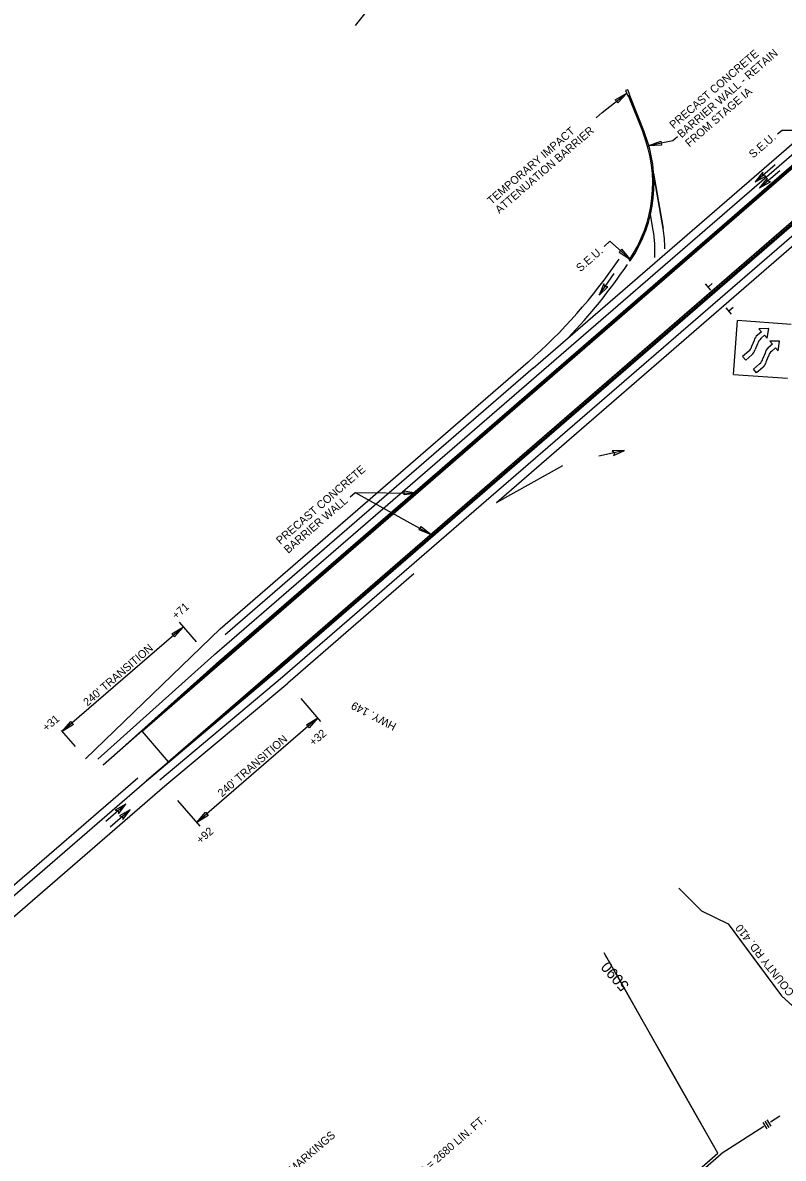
# Model space of a CAD drawing. Extents: x 259983 to 267998, y 211467 to 219827.
# Drawn here: x 261307 to 262447, y 216417 to 218119 of the extents above; entities that cross this region are included whole.
import ezdxf

# ---------------------------------------------------------------- set-up
doc = ezdxf.new("R2010")
doc.units = 0
for name, color, linetype in [('1', 7, 'Continuous'), ('Default', 7, 'Continuous'), ('Level 43', 7, 'Continuous'), ('Level 58', 7, 'Continuous'), ('R-W - CofA', 7, 'Continuous'), ('R_MOT', 7, 'Continuous'), ('R_MOT STAGE 1', 7, 'Continuous'), ('R_MOT STAGE 2', 7, 'Continuous'), ('STATIONING1', 7, 'Continuous')]:
    doc.layers.add(name, color=color, linetype=linetype)

msp = doc.modelspace()

# ---------------------------------------------------------------- linework, layer by layer
at = {"layer": '1'}
for p, q in [((262175.4, 217984.4), (262212.5, 218013.3)), ((262175.4, 217984.4), (262166.2, 217976.5)), ((262438.4, 217952.3), (262445.1, 217958)), ((262445.1, 217958), (262610.6, 217957)), ((262281.3, 217941.8), (262244.5, 217934.5)), ((262288.5, 217947.9), (262281.3, 217941.8)), ((262187, 217791.2), (262178.2, 217783.5)), ((262187, 217791.2), (262217.7, 217763.8)), ((261804.9, 217414.6), (261919.4, 217351.2))]:
    msp.add_line(p, q, dxfattribs=at)
for points in [[(262195.1, 218003.5), (262212.5, 218013.3), (262198.8, 217998.8)], [(262264.5, 217935.5), (262244.5, 217934.5), (262263.3, 217941.3)], [(262201, 217774.9), (262217.7, 217763.8), (262205, 217779.3)], [(261878.6, 217417.1), (261898.4, 217413.9), (261878.6, 217411.1)], [(261903.8, 217363.8), (261919.4, 217351.2), (261900.8, 217358.6)], [(261530.4, 217202.8), (261547.4, 217213.4), (261534.3, 217198.2)], [(261382.8, 217067), (261365.9, 217056.4), (261378.9, 217071.6)], [(261732, 217066.5), (261749, 217077.1), (261736, 217061.9)], [(261584.5, 216930.7), (261567.5, 216920.1), (261580.5, 216935.3)]]:
    msp.add_lwpolyline(points, close=True, dxfattribs=at)
msp.add_lwpolyline([(261797.3, 217408), (261804.9, 217414.6), (261898.4, 217413.9)], dxfattribs=at)
at = {"layer": 'Default'}
msp.add_line((261916, 218255.2), (261805, 218114.8), dxfattribs=at)
at = {"layer": 'Level 43'}
for points in [[(262405, 217880.2), (262435, 217906.2)], [(262411.5, 217871.5), (262441.6, 217897.4)], [(262170.8, 217710.6), (262193.5, 217743.1)], [(262209, 217477.5), (262170.2, 217469.1)], [(261461.1, 216947.7), (261431.1, 216921.7)], [(261467.7, 216939), (261437.7, 216913)]]:
    msp.add_lwpolyline(points, dxfattribs=at)
at = {"layer": 'Level 58'}
for points in [[(262416.1, 217894.8), (262405, 217880.2), (262421, 217889.1), (262416.3, 217890)], [(262422.7, 217886.1), (262411.5, 217871.5), (262427.6, 217880.4), (262422.9, 217881.3)], [(262178, 217727.5), (262170.8, 217710.6), (262184.1, 217723.2), (262179.4, 217722.9)], [(262192.2, 217470), (262209, 217477.5), (262190.6, 217477.3), (262194.4, 217474.3)], [(261450, 216933), (261461.1, 216947.7), (261445.1, 216938.7), (261449.8, 216937.8)], [(261456.5, 216924.3), (261467.7, 216939), (261451.6, 216930), (261456.3, 216929.1)]]:
    msp.add_lwpolyline(points, close=True, dxfattribs=at)
at = {"layer": 'R-W - CofA'}
for p, q in [((262428.8, 216465), (262422.8, 216474.1)), ((262422.7, 216461), (262416.7, 216470.2)), ((262425.7, 216463), (262419.8, 216472.1))]:
    msp.add_line(p, q, dxfattribs=at)
for points in [[(262290.2, 216821.6), (262324.3, 216787.7), (262364.1, 216767.9), (262444.5, 216660.2), (262530.1, 216582.3)], [(262290.2, 216821.6), (262291.3, 216820.5)], [(262294.9, 216817), (262324.3, 216787.7), (262364.1, 216767.9), (262408.4, 216708.5)], [(262348.6, 216424.2), (262178.4, 216724.8)], [(262182.6, 216717.3), (262178.4, 216724.8)], [(262188.3, 216707.2), (262185.2, 216712.7)], [(262194.1, 216697.1), (262190.9, 216702.6)], [(262408.4, 216708.5), (262444.5, 216660.2), (262514, 216596.9)], [(262277.6, 216549.5), (262196.7, 216692.5)], [(262328.8, 216406.9), (262348.6, 216424.2), (262277.6, 216549.5)], [(262441.9, 216479.9), (262427.8, 216470.8)], [(262417.6, 216464.3), (262353.9, 216423.3)], [(261724.8, 215893.9), (261785.3, 215946.6), (261867.3, 216004.8), (262348.6, 216424.2)], [(262186.1, 216277), (262353.9, 216423.3)]]:
    msp.add_lwpolyline(points, dxfattribs=at)
at = {"layer": 'R_MOT'}
for p, q in [((262338.1, 217718), (262330.1, 217727.3)), ((262334.1, 217722.7), (262340.5, 217728.2)), ((262369.1, 217682.2), (262361.1, 217691.5)), ((262365.1, 217686.8), (262371.6, 217692.4)), ((262372.4, 217591.7), (262378.2, 217672.4)), ((262459, 217666.7), (262378.2, 217672.5)), ((262414.4, 217655.7), (262408.2, 217650.4)), ((262425.1, 217660.3), (262410.5, 217660.2)), ((262414.4, 217655.7), (262410.5, 217660.2)), ((262419, 217650.3), (262413.3, 217645.4)), ((262422.9, 217645.8), (262419, 217650.3)), ((262422.9, 217645.8), (262425.1, 217660.3)), ((262403.3, 217642.5), (262400, 217634.3)), ((262408.1, 217637.5), (262404.7, 217628.9)), ((262430.7, 217636.9), (262424.5, 217631.5)), ((262430.7, 217636.9), (262426.8, 217641.4)), ((262441.4, 217641.4), (262426.8, 217641.4)), ((262435.3, 217631.5), (262429.6, 217626.5)), ((262439.2, 217627), (262435.3, 217631.5)), ((262439.2, 217627), (262441.4, 217641.4)), ((262395.1, 217626.3), (262386, 217618.4)), ((262390.7, 217613), (262386, 217618.4)), ((262399.8, 217620.9), (262390.7, 217613)), ((262419.6, 217623.6), (262416.3, 217615.4)), ((262424.4, 217618.7), (262421, 217610.1)), ((262411.4, 217607.5), (262402.3, 217599.6)), ((262407, 217594.2), (262402.3, 217599.6)), ((262416.1, 217602.1), (262407, 217594.2)), ((262372.4, 217591.7), (262453.2, 217585.9))]:
    msp.add_line(p, q, dxfattribs=at)
for centre, major_axis in [((262419.5, 217636.8), (-11.6, 13.4)), ((262383.7, 217640), (11.6, -13.4)), ((262424.6, 217631.7), (-11.6, 13.4)), ((262435.9, 217617.9), (-11.6, 13.4)), ((262388.5, 217634.6), (11.6, -13.4)), ((262400.1, 217621.2), (11.6, -13.4)), ((262440.9, 217612.9), (-11.6, 13.4)), ((262404.8, 217615.7), (11.6, -13.4))]:
    msp.add_ellipse(centre, major_axis=major_axis, ratio=0.9, start_param=6.26006, end_param=6.849246, dxfattribs=at)
at = {"layer": 'R_MOT STAGE 1'}
for p, q in [((262072.1, 217601.2), (262850.7, 218275.2)), ((262844.1, 218235.1), (261603.1, 217160.8)), ((262845.4, 218233.6), (261604.4, 217159.3)), ((262782.9, 218200.4), (261594, 217171.3)), ((261601.8, 217162.3), (262790.6, 218191.5)), ((262214.5, 218009.7), (262216.4, 218010.5)), ((262214.5, 218009.7), (262236.7, 217953.9)), ((262216.4, 218010.5), (262238.5, 217954.7)), ((262522.7, 217954.3), (262302.4, 217763.5)), ((261685.6, 217150.2), (262571.3, 217917)), ((261686.9, 217148.7), (262572.7, 217915.5)), ((261688.2, 217147.1), (262574.1, 217914.1)), ((262009, 217409), (262582.1, 217905.1)), ((262016.8, 217399.9), (262589.9, 217896.1)), ((262252.6, 217893.6), (262266.7, 217810.4)), ((262266.7, 217810.4), (262252.6, 217893.6)), ((262438.1, 217881), (262438.1, 217881)), ((261865.1, 217305.6), (262473.9, 217832.7)), ((262251.9, 217807.9), (262247.9, 217831.6)), ((262215.8, 217762.9), (262217.4, 217761.8)), ((262293.4, 217755.7), (262267.1, 217733)), ((262302.1, 217763.3), (262293.4, 217755.7)), ((262267.1, 217733), (262223.8, 217695.5)), ((262223.8, 217695.5), (262169.5, 217648.4)), ((262169.4, 217648.4), (261825.9, 217351)), ((261602.5, 217210.5), (262064.3, 217610.3)), ((262072.1, 217601.2), (261610.3, 217201.4)), ((262016.8, 217399.9), (262116.4, 217455.3)), ((261696.1, 217138.2), (262009, 217409)), ((261825.9, 217351), (261485.7, 217056.5)), ((261825.9, 217351), (261825.9, 217351)), ((261524.9, 217011.1), (261865.1, 217305.6)), ((261892.8, 217292.6), (261704, 217129.1)), ((261865.1, 217305.6), (261865.1, 217305.6)), ((261400.6, 217015.6), (261602.5, 217210.5)), ((261419.3, 217014.9), (261593.8, 217171.2)), ((261427.3, 217005.9), (261601.8, 217162.3)), ((261603.1, 217160.8), (261427.3, 217005.9)), ((261601.8, 217162.3), (261603.1, 217160.8)), ((261686.9, 217148.7), (261492, 216982.6)), ((261492, 216982.6), (261688.3, 217147.2)), ((261512.2, 216984.2), (261696.3, 217138.3)), ((261519.9, 216975), (261704, 217129.1)), ((261485.7, 217056.5), (261485.7, 217056.5)), ((261485.7, 217056.5), (261485.7, 217056.5)), ((261485.7, 217056.5), (261485.7, 217056.5)), ((261485.7, 217056.5), (261524.9, 217011.1)), ((261173.7, 216707.1), (261504.2, 216993.2)), ((261189.4, 216688.9), (261519.9, 216975))]:
    msp.add_line(p, q, dxfattribs=at)
msp.add_lwpolyline([(262217.1, 218010.8), (262214, 218018.5), (262210.5, 218017.1), (262213.7, 218009.3)], close=True, dxfattribs=at)
for centre, radius, start, end in [((262045.7, 217878.1), 205.5, 325.8833, 21.6456), ((262045.7, 217878.1), 207.5, 325.8833, 22.076), ((262062.1, 217775.8), 192.5, 357.5708, 9.5976), ((262062.1, 217775.8), 192.5, 357.3485, 9.5976), ((262062.1, 217775.8), 207.5, 1.1658, 9.5976), ((261546.1, 218205.8), 789.4, 311.0269, 326.027), ((261543.2, 218207.1), 807.5, 316.0285, 326.0667), ((262300.7, 217765.2), 2.41, 307.5819, 315.0819), ((262169.3, 217648.6), 0.271, 299.5898, 321.0962)]:
    msp.add_arc(centre, radius, start, end, dxfattribs=at)
at = {"layer": 'R_MOT STAGE 2'}
for p, q in [((261547.4, 217213.4), (261365.9, 217056.4)), ((261567, 217190.8), (261541.4, 217220.3)), ((261753.8, 217071.6), (261723.9, 217106.1)), ((261749, 217077.1), (261567.5, 216920.1)), ((261385.5, 217033.7), (261364.7, 217057.8)), ((261071.3, 216634.3), (261479, 216987.2)), ((261572.4, 216914.5), (261538.9, 216953.1))]:
    msp.add_line(p, q, dxfattribs=at)

# ---------------------------------------------------------------- texts
at = {"layer": '1'}
for s, rotation, p in [('PRECAST CONCRETE', 40.8833, (262282.6, 217959.1)), ('BARRIER WALL - RETAIN', 40.8833, (262294.4, 217945.4)), ('FROM STAGE IA', 40.8833, (262306.2, 217931.8)), ('TEMPORARY IMPACT', 40.8733, (262009.5, 217845.5)), ('ATTENUATION BARRIER', 40.8733, (262021.3, 217831.9)), ('S.E.U.', 40.8933, (262401.8, 217915.1)), ('S.E.U.', 40.8733, (262142.7, 217744.7)), ('PRECAST CONCRETE', 40.8833, (261692.8, 217336.1)), ('BARRIER WALL', 40.8833, (261704.6, 217322.5)), ("240' TRANSITION", 40.8733, (261403.7, 217093.7)), ('HWY. 149', 152.3599, (261868, 217067.8)), ("240' TRANSITION", 40.8733, (261605.3, 216957.4)), ('COUNTY RD. 410', 127.9922, (262464.1, 216665.5))]:
    msp.add_text(s, height=12, rotation=rotation, dxfattribs=at).set_placement(p)
at = {"layer": 'Default'}
for s, p in [('FURNISHING AND INSTALLING PRECAST CONCRETE BARRIER = 2680 LIN. FT.', (261546.7, 216078.7)), ('REMOVABLE CONSTRUCTION PAVEMENT MARKINGS', (261461.6, 216177.1))]:
    msp.add_text(s, height=12, rotation=40.8833, dxfattribs=at).set_placement(p)
at = {"layer": 'R_MOT STAGE 2'}
for s, p in [('+71', (261536.6, 217223.9)), ('+31', (261342.4, 217055.8)), ('+32', (261742.5, 217033.9)), ('+92', (261573.2, 216887.3))]:
    msp.add_text(s, height=12, rotation=40.8821, dxfattribs=at).set_placement(p)
at = {"layer": 'STATIONING1'}
msp.add_text('5090', height=16.5, rotation=130.8833, dxfattribs=at).set_placement((262216.8, 216676))

doc.saveas('drawing.dxf')
